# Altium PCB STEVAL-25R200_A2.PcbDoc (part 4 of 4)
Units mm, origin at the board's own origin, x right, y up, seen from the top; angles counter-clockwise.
Board outline 84.5 x 100 mm, 4 copper layers (Top Layer, F2, F3, Bottom Layer), stack 0.78 mm thick; 272 components, 152 nets, 679 pads, 380 vias.
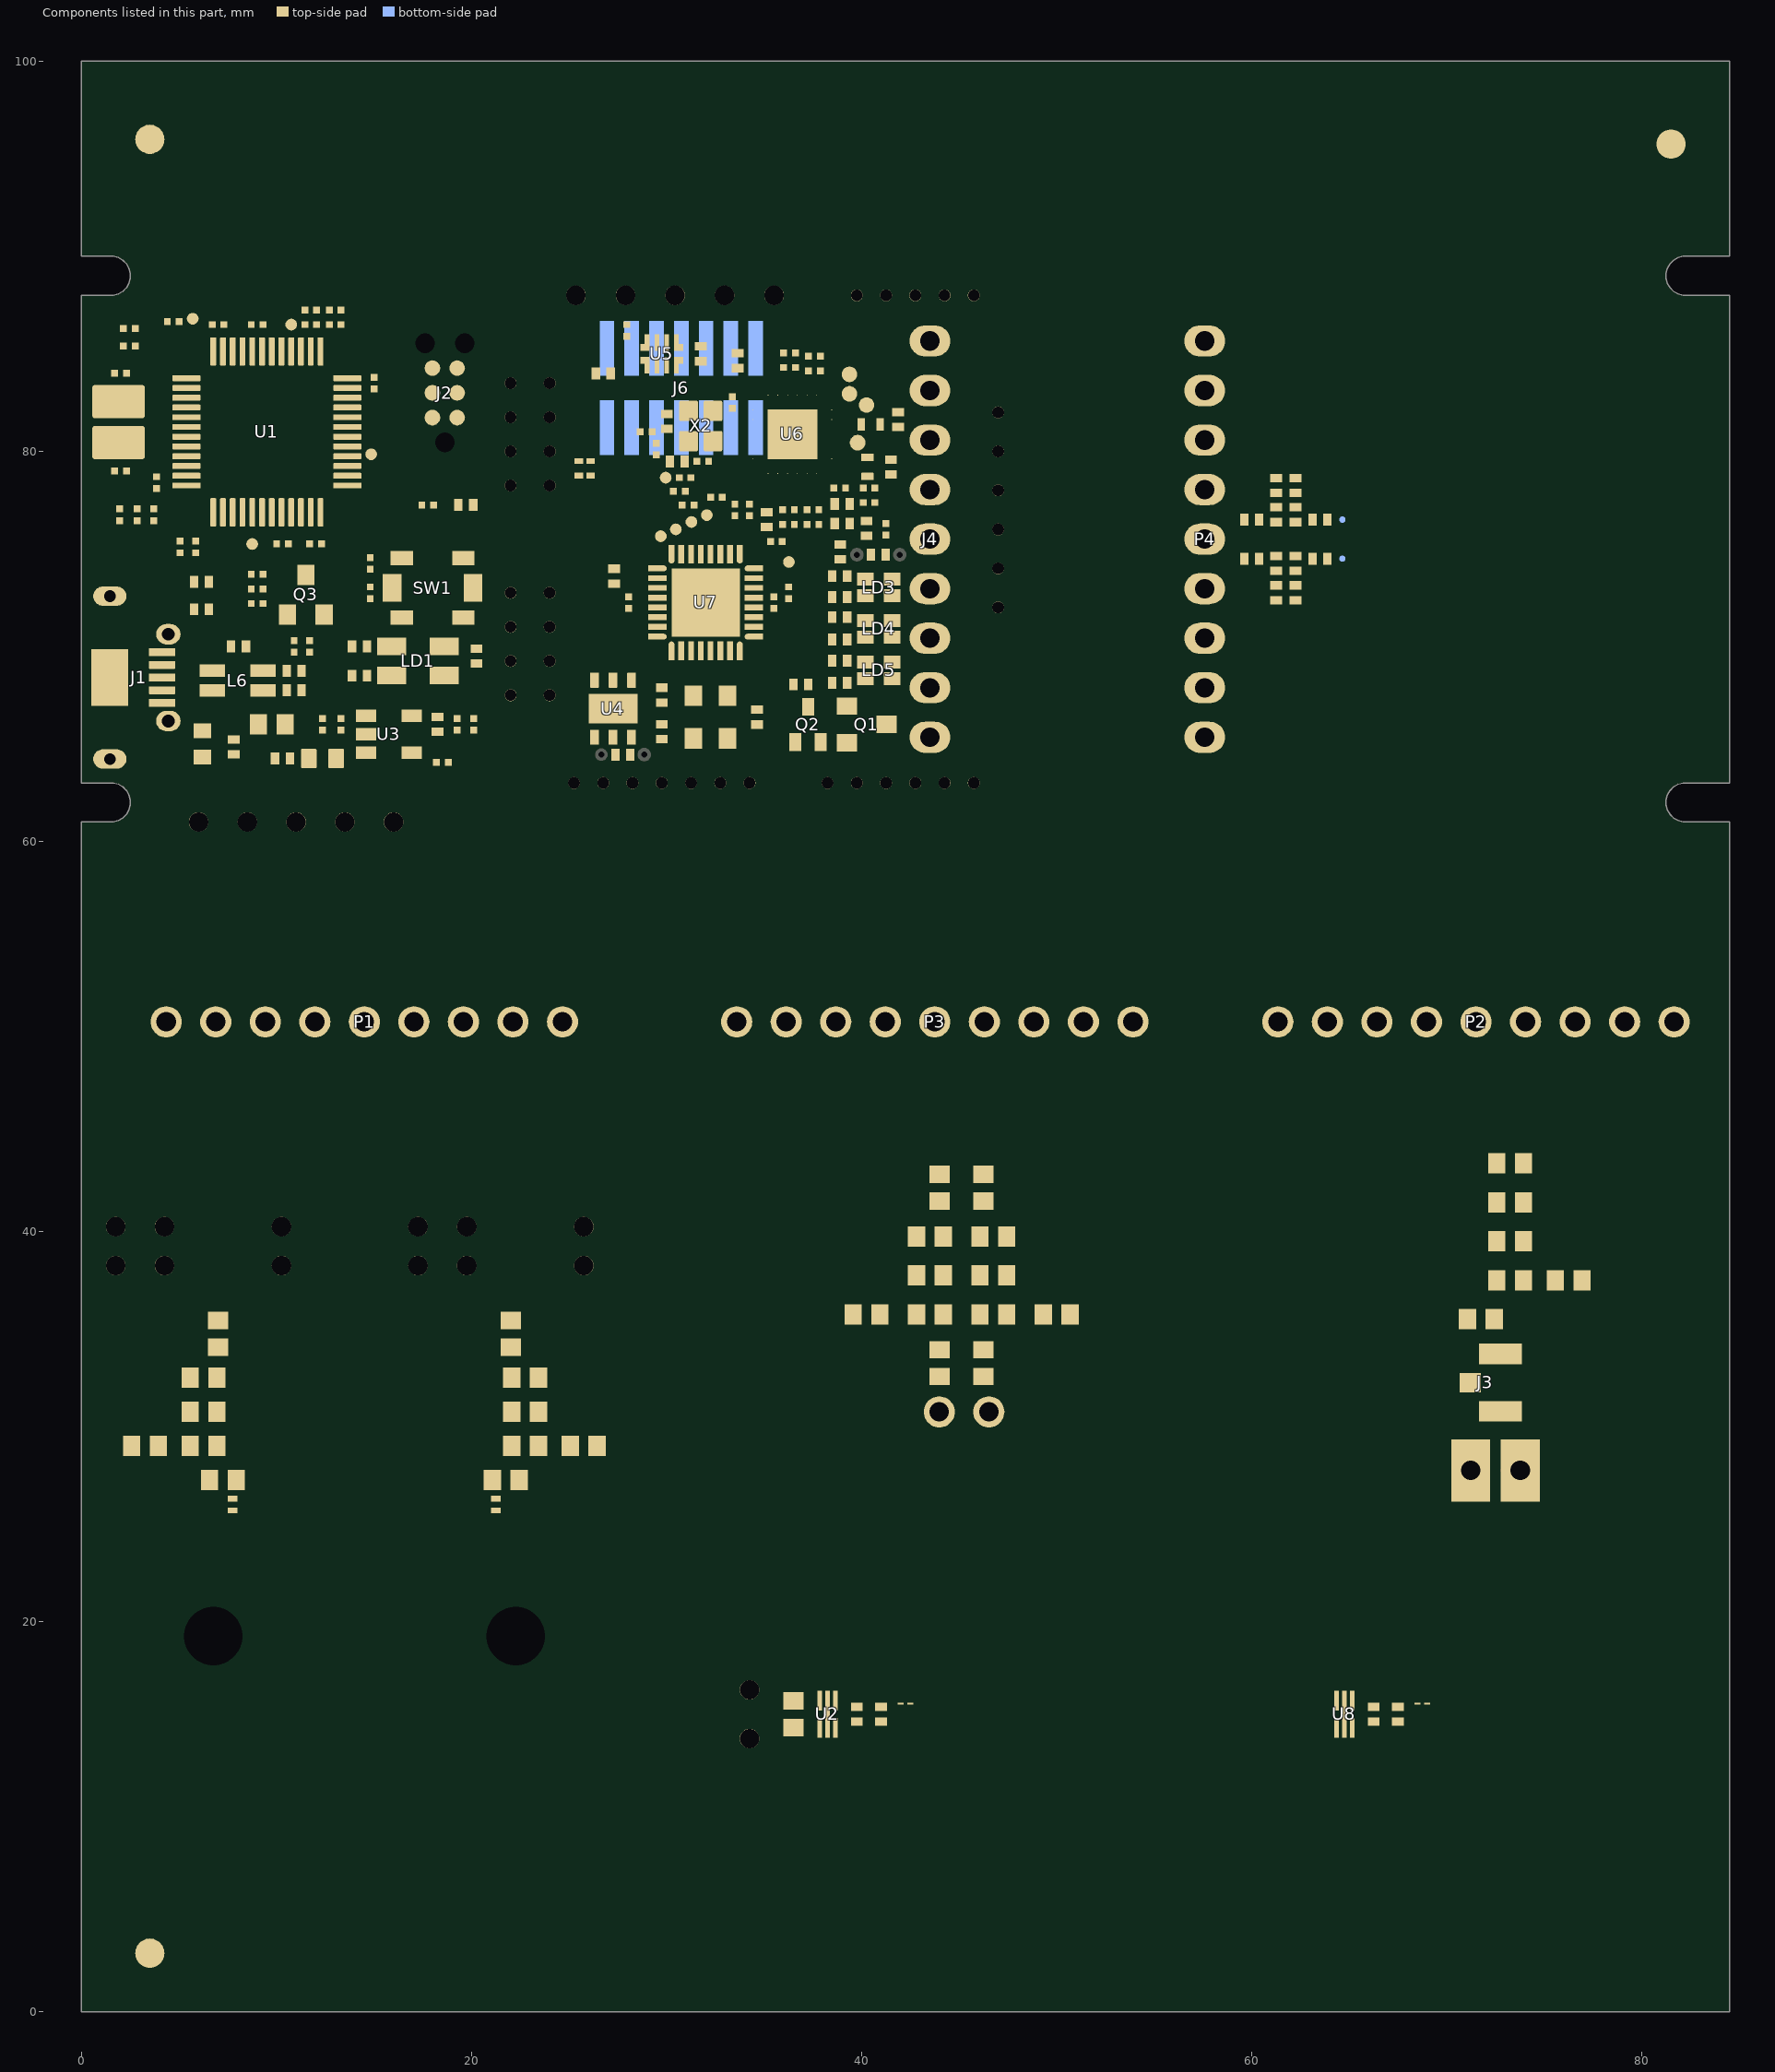
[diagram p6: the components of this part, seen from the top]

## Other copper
Top Layer:
  rectangle net VDD_RF: 41.075,74.4 42.25,75
  region net NetC79_2: 40.625,75 39.45,75 39.45,74.4 40.625,74.4
  region net NetR58_1: 27.525,64.75 26.35,64.75 26.35,64.15 27.525,64.15
  rectangle net VDD_RF: 27.975,64.15 29.15,64.75
  rectangle net NetJP2_2: 45.52,28.45 47.52,31.65
  rectangle net NetJP2_1: 42.98,28.45 44.98,31.65
  region net G0_VBUS: 30.95,86 30.45,86 30.45,85.7 30.95,85.7
  region net G0_GND_USB: 30.95,84.3 30.45,84.3 30.45,84 30.95,84
  rectangle net G0_GND_USB: 28.55,84 29.05,84.3
  region net GND_HUB: 27.445,24.445 ccw(c25.5,22.5) 25.5,25.25 23.75,25.25 cw(c23.75,25.5) 23.573,25.323 cw(c23.75,25.5) 23.5,25.5 23.5,25.8 23,25.8 23,25.5 ccw(c23.75,25.5) 23.22,24.97 ccw(c23.75,25.5) 23.75,24.75 25.5,24.75 cw(c25.5,22.5) 27.091,24.091 cw(c25.5,22.5) 27.75,22.5 27.75,16 cw(c25.5,16) 27.091,14.409 cw(c25.5,16) 25.5,13.75 23.076,13.75 21.702,14.666 ccw(c21.424,14.25) 21.569,14.729 ccw(c21.424,14.25) 21.424,14.75 19,14.75 cw(c19,16) 18.116,15.116 cw(c19,16) 17.75,16 17.75,22.5 cw(c19,22.5) 18.116,23.384 cw(c19,22.5) 19,23.75 25.5,23.75 cw(c25.5,22.5) 26.384,23.384 cw(c25.5,22.5) 26.75,22.5 26.75,16 cw(c25.5,16) 26.384,15.116 cw(c25.5,16) 25.5,14.75 23.076,14.75 21.702,15.666 ccw(c21.424,15.25) 21.569,15.729 ccw(c21.424,15.25) 21.424,15.75 19,15.75 cw(c19,16) 18.823,15.823 cw(c19,16) 18.75,16 18.75,22.5 cw(c19,22.5) 18.823,22.677 cw(c19,22.5) 19,22.75 25.5,22.75 cw(c25.5,22.5) 25.677,22.677 cw(c25.5,22.5) 25.75,22.5 25.75,16 cw(c25.5,16) 25.677,15.823 cw(c25.5,16) 25.5,15.75 23.309,15.75 22.362,16.224 ccw(c22.25,16) 22.026,16.112 ccw(c22.25,16) 22.138,15.776 23.085,15.303 ccw(c23.309,15.75) 23.194,15.263 ccw(c23.309,15.75) 23.309,15.25 25.5,15.25 ccw(c25.5,16) 26.03,15.47 ccw(c25.5,16) 26.25,16 26.25,22.5 ccw(c25.5,22.5) 26.03,23.03 ccw(c25.5,22.5) 25.5,23.25 19,23.25 ccw(c19,22.5) 18.47,23.03 ccw(c19,22.5) 18.25,22.5 18.25,16 ccw(c19,16) 18.47,15.47 ccw(c19,16) 19,15.25 21.424,15.25 22.798,14.334 ccw(c23.076,14.75) 22.931,14.271 ccw(c23.076,14.75) 23.076,14.25 25.5,14.25 ccw(c25.5,16) 26.737,14.763 ccw(c25.5,16) 27.25,16 27.25,22.5 ccw(c25.5,22.5) 26.737,23.737 ccw(c25.5,22.5) 25.5,24.25 19,24.25 ccw(c19,22.5) 17.763,23.737 ccw(c19,22.5) 17.25,22.5 17.25,16 ccw(c19,16) 17.763,14.763 ccw(c19,16) 19,14.25 21.424,14.25 22.798,13.334 ccw(c23.076,13.75) 22.931,13.271 ccw(c23.076,13.75) 23.076,13.25 25.5,13.25 ccw(c25.5,16) 27.445,14.055 ccw(c25.5,16) 28.25,16 28.25,22.5 ccw(c25.5,22.5)
  region net GND_HUB: 21.5,25.8 21,25.8 21,25.5 cw(c20.75,25.5) 20.927,25.323 cw(c20.75,25.5) 20.75,25.25 19,25.25 ccw(c19,22.5) 17.055,24.445 ccw(c19,22.5) 16.25,22.5 16.25,16 ccw(c19,16) 17.055,14.055 ccw(c19,16) 19,13.25 21.191,13.25 22.138,12.776 ccw(c22.25,13) 22.474,12.888 ccw(c22.25,13) 22.362,13.224 21.415,13.697 ccw(c21.191,13.251) 21.306,13.737 ccw(c21.191,13.251) 21.191,13.75 19,13.75 cw(c19,16) 17.409,14.409 cw(c19,16) 16.75,16 16.75,22.5 cw(c19,22.5) 17.409,24.091 cw(c19,22.5) 19,24.75 20.75,24.75 ccw(c20.75,25.5) 21.28,24.97 ccw(c20.75,25.5) 21.5,25.5
  region net GND_HUB: 6,25.8 5.5,25.8 5.5,25.5 cw(c5.25,25.5) 5.427,25.323 cw(c5.25,25.5) 5.25,25.25 3.5,25.25 ccw(c3.5,22.5) 1.555,24.445 ccw(c3.5,22.5) 0.75,22.5 0.75,16 ccw(c3.5,16) 1.555,14.055 ccw(c3.5,16) 3.5,13.25 5.691,13.25 6.638,12.776 ccw(c6.75,13) 6.974,12.888 ccw(c6.75,13) 6.862,13.224 5.915,13.697 ccw(c5.691,13.25) 5.806,13.737 ccw(c5.691,13.25) 5.691,13.75 3.5,13.75 cw(c3.5,16) 1.909,14.409 cw(c3.5,16) 1.25,16 1.25,22.5 cw(c3.5,22.5) 1.909,24.091 cw(c3.5,22.5) 3.5,24.75 5.25,24.75 ccw(c5.25,25.5) 5.78,24.97 ccw(c5.25,25.5) 6,25.5
  region net GND_HUB: 11.945,24.445 ccw(c10,22.5) 10,25.25 8.25,25.25 cw(c8.25,25.5) 8.073,25.323 cw(c8.25,25.5) 8,25.5 8,25.8 7.5,25.8 7.5,25.5 ccw(c8.25,25.5) 7.72,24.97 ccw(c8.25,25.5) 8.25,24.75 10,24.75 cw(c10,22.5) 11.591,24.091 cw(c10,22.5) 12.25,22.5 12.25,16 cw(c10,16) 11.591,14.409 cw(c10,16) 10,13.75 7.576,13.75 6.202,14.666 ccw(c5.925,14.25) 6.069,14.729 ccw(c5.924,14.251) 5.924,14.75 3.5,14.75 cw(c3.5,16) 2.616,15.116 cw(c3.5,16) 2.25,16 2.25,22.5 cw(c3.5,22.5) 2.616,23.384 cw(c3.5,22.5) 3.5,23.75 10,23.75 cw(c10,22.5) 10.884,23.384 cw(c10,22.5) 11.25,22.5 11.25,16 cw(c10,16) 10.884,15.116 cw(c10,16) 10,14.75 7.576,14.75 6.202,15.666 ccw(c5.925,15.25) 6.069,15.729 ccw(c5.924,15.251) 5.924,15.75 3.5,15.75 cw(c3.5,16) 3.323,15.823 cw(c3.5,16) 3.25,16 3.25,22.5 cw(c3.5,22.5) 3.323,22.677 cw(c3.5,22.5) 3.5,22.75 10,22.75 cw(c10,22.5) 10.177,22.677 cw(c10,22.5) 10.25,22.5 10.25,16 cw(c10,16) 10.177,15.823 cw(c10,16) 10,15.75 7.809,15.75 6.862,16.224 ccw(c6.75,16) 6.526,16.112 ccw(c6.75,16) 6.638,15.776 7.585,15.303 ccw(c7.809,15.75) 7.694,15.263 ccw(c7.809,15.75) 7.809,15.25 10,15.25 ccw(c10,16) 10.53,15.47 ccw(c10,16) 10.75,16 10.75,22.5 ccw(c10,22.5) 10.53,23.03 ccw(c10,22.5) 10,23.25 3.5,23.25 ccw(c3.5,22.5) 2.97,23.03 ccw(c3.5,22.5) 2.75,22.5 2.75,16 ccw(c3.5,16) 2.97,15.47 ccw(c3.5,16) 3.5,15.25 5.924,15.25 7.298,14.334 ccw(c7.576,14.75) 7.431,14.271 ccw(c7.576,14.75) 7.576,14.25 10,14.25 ccw(c10,16) 11.237,14.763 ccw(c10,16) 11.75,16 11.75,22.5 ccw(c10,22.5) 11.237,23.737 ccw(c10,22.5) 10,24.25 3.5,24.25 ccw(c3.5,22.5) 2.263,23.737 ccw(c3.5,22.5) 1.75,22.5 1.75,16 ccw(c3.5,16) 2.263,14.763 ccw(c3.5,16) 3.5,14.25 5.924,14.25 7.298,13.334 ccw(c7.576,13.75) 7.431,13.271 ccw(c7.576,13.75) 7.576,13.25 10,13.25 ccw(c10,16) 11.945,14.055 ccw(c10,16) 12.75,16 12.75,22.5 ccw(c10,22.5)
  text ".text_ident_couches" at 25.5,108.5 h1.5
  text "- TOP LAYER -" at 30,104.25 h1.5
F2:
  pour cut-out: 70.65,32.85 71.65,32.85 71.65,33.15 73.85,33.15 73.85,31.35 71.65,31.35 71.65,31.65 70.65,31.65
  text ".text_ident_couches" at 25.5,108.5 h1.5
  text "- LAYER 2 -" at 30.75,104.25 h1.5
F3:
  pour cut-out: 70.65,32.85 71.65,32.85 71.65,33.15 73.85,33.15 73.85,31.35 71.65,31.35 71.65,31.65 70.65,31.65
  text ".text_ident_couches" at 54.8,108.25 h1.5
  text "- LAYER 3 -" at 47.75,104.25 h1.5
Bottom Layer:
  region net GND_HUB: 27.445,24.445 cw(c25.5,22.5) 28.25,22.5 28.25,16 cw(c25.5,16) 27.445,14.055 cw(c25.5,16) 25.5,13.25 23.309,13.25 22.362,12.776 cw(c22.25,13) 22.026,12.888 cw(c22.25,13) 22.138,13.224 23.085,13.697 cw(c23.309,13.25) 23.194,13.737 cw(c23.309,13.25) 23.309,13.75 25.5,13.75 ccw(c25.5,16) 27.091,14.409 ccw(c25.5,16) 27.75,16 27.75,22.5 ccw(c25.5,22.5) 27.091,24.091 ccw(c25.5,22.5) 25.5,24.75 19,24.75 ccw(c19,22.5) 17.409,24.091 ccw(c19,22.5) 16.75,22.5 16.75,16 ccw(c19,16) 17.409,14.409 ccw(c19,16) 19,13.75 21.424,13.75 22.798,14.666 cw(c23.076,14.25) 22.931,14.729 cw(c23.076,14.25) 23.076,14.75 25.5,14.75 ccw(c25.5,16) 26.384,15.116 ccw(c25.5,16) 26.75,16 26.75,22.5 ccw(c25.5,22.5) 26.384,23.384 ccw(c25.5,22.5) 25.5,23.75 19,23.75 ccw(c19,22.5) 18.116,23.384 ccw(c19,22.5) 17.75,22.5 17.75,16 ccw(c19,16) 18.116,15.116 ccw(c19,16) 19,14.75 21.424,14.75 22.798,15.666 cw(c23.076,15.25) 22.931,15.729 cw(c23.076,15.25) 23.076,15.75 25.5,15.75 ccw(c25.5,16) 25.677,15.823 ccw(c25.5,16) 25.75,16 25.75,22.5 ccw(c25.5,22.5) 25.677,22.677 ccw(c25.5,22.5) 25.5,22.75 19,22.75 ccw(c19,22.5) 18.823,22.677 ccw(c19,22.5) 18.75,22.5 18.75,16 ccw(c19,16) 18.823,15.823 ccw(c19,16) 19,15.75 21.191,15.75 22.138,16.224 cw(c22.25,16) 22.474,16.112 cw(c22.25,16) 22.362,15.776 21.415,15.303 cw(c21.191,15.75) 21.306,15.263 cw(c21.191,15.75) 21.191,15.25 19,15.25 cw(c19,16) 18.47,15.47 cw(c19,16) 18.25,16 18.25,22.5 cw(c19,22.5) 18.47,23.03 cw(c19,22.5) 19,23.25 25.5,23.25 cw(c25.5,22.5) 26.03,23.03 cw(c25.5,22.5) 26.25,22.5 26.25,16 cw(c25.5,16) 26.03,15.47 cw(c25.5,16) 25.5,15.25 23.076,15.25 21.702,14.334 cw(c21.424,14.75) 21.569,14.271 cw(c21.424,14.75) 21.424,14.25 19,14.25 cw(c19,16) 17.763,14.763 cw(c19,16) 17.25,16 17.25,22.5 cw(c19,22.5) 17.763,23.737 cw(c19,22.5) 19,24.25 25.5,24.25 cw(c25.5,22.5) 26.737,23.737 cw(c25.5,22.5) 27.25,22.5 27.25,16 cw(c25.5,16) 26.737,14.763 cw(c25.5,16) 25.5,14.25 23.076,14.25 21.702,13.334 cw(c21.424,13.75) 21.569,13.271 cw(c21.424,13.75) 21.424,13.25 19,13.25 cw(c19,16) 17.055,14.055 cw(c19,16) 16.25,16 16.25,22.5 cw(c19,22.5) 17.055,24.445 cw(c19,22.5) 19,25.25 25.5,25.25 cw(c25.5,22.5)
  region net GND_HUB: 11.945,24.445 cw(c10,22.5) 12.75,22.5 12.75,16 cw(c10,16) 11.945,14.055 cw(c10,16) 10,13.25 7.809,13.25 6.862,12.776 cw(c6.75,13) 6.526,12.888 cw(c6.75,13) 6.638,13.224 7.585,13.697 cw(c7.809,13.25) 7.694,13.737 cw(c7.809,13.25) 7.809,13.75 10,13.75 ccw(c10,16) 11.591,14.409 ccw(c10,16) 12.25,16 12.25,22.5 ccw(c10,22.5) 11.591,24.091 ccw(c10,22.5) 10,24.75 3.5,24.75 ccw(c3.5,22.5) 1.909,24.091 ccw(c3.5,22.5) 1.25,22.5 1.25,16 ccw(c3.5,16) 1.909,14.409 ccw(c3.5,16) 3.5,13.75 5.924,13.75 7.298,14.666 cw(c7.576,14.25) 7.431,14.729 cw(c7.576,14.25) 7.576,14.75 10,14.75 ccw(c10,16) 10.884,15.116 ccw(c10,16) 11.25,16 11.25,22.5 ccw(c10,22.5) 10.884,23.384 ccw(c10,22.5) 10,23.75 3.5,23.75 ccw(c3.5,22.5) 2.616,23.384 ccw(c3.5,22.5) 2.25,22.5 2.25,16 ccw(c3.5,16) 2.616,15.116 ccw(c3.5,16) 3.5,14.75 5.924,14.75 7.298,15.666 cw(c7.576,15.25) 7.431,15.729 cw(c7.576,15.25) 7.576,15.75 10,15.75 ccw(c10,16) 10.177,15.823 ccw(c10,16) 10.25,16 10.25,22.5 ccw(c10,22.5) 10.177,22.677 ccw(c10,22.5) 10,22.75 3.5,22.75 ccw(c3.5,22.5) 3.323,22.677 ccw(c3.5,22.5) 3.25,22.5 3.25,16 ccw(c3.5,16) 3.323,15.823 ccw(c3.5,16) 3.5,15.75 5.691,15.75 6.638,16.224 cw(c6.75,16) 6.974,16.112 cw(c6.75,16) 6.862,15.776 5.915,15.303 cw(c5.691,15.75) 5.806,15.263 cw(c5.691,15.75) 5.691,15.25 3.5,15.25 cw(c3.5,16) 2.97,15.47 cw(c3.5,16) 2.75,16 2.75,22.5 cw(c3.5,22.5) 2.97,23.03 cw(c3.5,22.5) 3.5,23.25 10,23.25 cw(c10,22.5) 10.53,23.03 cw(c10,22.5) 10.75,22.5 10.75,16 cw(c10,16) 10.53,15.47 cw(c10,16) 10,15.25 7.576,15.25 6.202,14.334 cw(c5.924,14.75) 6.069,14.271 cw(c5.924,14.75) 5.924,14.25 3.5,14.25 cw(c3.5,16) 2.263,14.763 cw(c3.5,16) 1.75,16 1.75,22.5 cw(c3.5,22.5) 2.263,23.737 cw(c3.5,22.5) 3.5,24.25 10,24.25 cw(c10,22.5) 11.237,23.737 cw(c10,22.5) 11.75,22.5 11.75,16 cw(c10,16) 11.237,14.763 cw(c10,16) 10,14.25 7.576,14.25 6.202,13.334 cw(c5.924,13.75) 6.069,13.271 cw(c5.924,13.75) 5.924,13.25 3.5,13.25 cw(c3.5,16) 1.555,14.055 cw(c3.5,16) 0.75,16 0.75,22.5 cw(c3.5,22.5) 1.555,24.445 cw(c3.5,22.5) 3.5,25.25 10,25.25 cw(c10,22.5)
  text ".text_ident_couches" at 54.6,108.25 h1.5
  text "- BOTTOM LAYER -" at 50.25,104.25 h1.5

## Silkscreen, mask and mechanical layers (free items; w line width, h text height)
Top Overlay:
  drawing of 607 lines, arcs and shapes, not listed
  text ".text_ident_couches" at 25.5,108.5 h1.5
  text "- TOP OVERLAY -" at 28.75,104.25 h1.5
  text "STEVAL$25R200AA" at 69.108,98.3 h1.8
  text "STEVAL-25R200A" at 25.833,93.3 h6
  text "STLink" at 8.118,91 h2
  text "ST25R200 Module" at 27.25,91 h2
  text "Main NFC Antenna" at 58,91 h2
  text "GND" at 17.28,86.55 h1.3
  text "USB" at 32.347,85.53 h1.7
  text "TCK" at 16.798,85.231 h1.3 r90
  text "RST" at 21.5,85.23 h1.3 r90
  text "ANT" at 42.2,83.107 h1.7 r90
  text "VCC" at 20.587,78.156 h1.3 r90
  text "TMS" at 17.15,78.13 h1.3 r90
  text "ST25R200" at 28.26,76.172 h1.4 r90
  text "RESET" at 15.228,75.15 h1.7
  text "USB" at 1.075,73.3 h1.7
  text "L1" at 36.8,73.31 h1.3
  text "ST25" at 72.893,72.532 h1.65
  text "L2" at 36.8,71.13 h1.3
  text "L3" at 36.8,68.92 h1.3
  text "STEVAL-25R200" at 26.74,68.685 h1.38 r90
  text "NFC Antenna 20x20mm" at 65.469,64.212 h1.6
  text "Dual Antenna Hub" at 2.25,47.5 h3
  text "Flexible Antenna" at 33,47.5 h3
  text "50 Ohms Antenna Interface" at 59.5,45 h3
  text "Flex Antenna" at 41.4,21.412 h1.7 r90
  text "ANT1" at 3.213,7.5 h2
  text "ANT2" at 18.562,7.5 h2
  text "Tag1 : ST25TV" at 33.938,7 h2
  text "Tag2 : ST25TN" at 61.938,7 h2
  text "12x12mm" at 1.604,6 h1.6
  text "12x12mm" at 17.604,6 h1.6
  text "10x5mm" at 38.604,6 h1.6
  text "10x5mm" at 66.604,6 h1.6
  text "ST25R200 Evaluation Board : NFC made easy" at 7.134,1 h3.8
Bottom Overlay:
  drawing of 432 lines, arcs and shapes, not listed
  text ".text_ident_couches" at 54.4,108.25 h1.5
  text "- BOTTOM OVERLAY -" at 53,104.25 h1.5
  text "MM0005A1" at 20.2,86.517 h1.5
  text "FCC ID: YCPR200AD1" at 9.23,85.873 h2.3 r90
  text "IC: 8976A-R200AD1" at 11.19,85.858 h2.3 r90
  text "MM0003A1" at 82.95,85.817 h1.5
  text "STEVAL-25R200SA" at 7.33,85.623 h2.3 r90
  text "GND" at 56.15,85.12 h1.5
  text "FOR EVALUATION ONLY" at 13.67,84.52 h1.8 r90
  text "VDD" at 36.55,83.382 h1.5 r270
  text "DAC" at 37.8,83.357 h1.5 r270
  text "ADC" at 39,83.26 h1.5 r270
  text "VCCSTLK" at 20.65,83.05 h1.5
  text "MM0004A1" at 33.4,82.816 h1.39
  text "RFI2" at 56.05,82.6 h1.5
  text "SCL" at 40.2,82.487 h1.5 r270
  text "SDA" at 41.298,82.475 h1.5 r270
  text "GND" at 20.65,81.25 h1.5
  text "GND" at 44.85,80.947 h1.5 r270
  text "STLink" at 25.3,80.661 h1.39 r270
  text "GND" at 56.15,80.04 h1.5
  text "I2" at 44.9,79.55 h1.5 r270
  text "RX" at 20.91,79.33 h1.5
  text "UART" at 18.35,78.4 h1.5
  text "TX" at 20.9,77.78 h1.5
  text "RFO2" at 56.15,77.5 h1.5
  text "O2" at 44.8,77.15 h1.5 r270
  text "O1" at 44.8,75.15 h1.5 r270
  text "RFO1" at 56.162,74.95 h1.5
  text "I1" at 44.8,73.6 h1.5 r270
  text "GND" at 56.15,72.42 h1.5
  text "5V_USB / CHGR" at 20.7,71.93 h1.5
  text "STEVAL-25R200A" at 82.013,71.62 h2.8
  text "SWDIO" at 20.65,70.55 h1.5
  text "GND" at 44.8,70.247 h1.5 r270
  text "RFI1" at 56.041,69.95 h1.5
  text "TCK" at 20.65,68.8 h1.5
  text "I2S2" at 28.53,67.39 h1.5
  text "GND" at 56.15,67.34 h1.5
  text "AUXIN" at 41.01,67.22 h1.5
  text "RST" at 20.65,67.05 h1.5
  text "SD" at 26.2,65.02 h1.5 r270
  text "AUXOUT" at 45.8,64.9 h1.5 r270
  text "CK" at 27.75,64.82 h1.5 r270
  text "GND" at 56.15,64.8 h1.5
  text "GND" at 44.7,64.6 h1.5 r270
  text "TX" at 37.806,64.204 h1.5 r270
  text "RX" at 39.207,64.204 h1.5 r270
  text "WS" at 24.8,64.147 h1.5 r270
  text "GND" at 29.36,64.15 h1.5 r270
  text "5VUSB" at 30.8,64.147 h1.5 r270
  text "5VUSB" at 32.3,64.147 h1.5 r270
  text "GND" at 33.8,64.147 h1.5 r270
  text "GND" at 40.645,64.114 h1.5 r270
  text "STEVAL$25R200AA" at 83.564,63.69 h2.2
  text "MM0006A1" at 28,58.217 h1.5
  text "MM0009A1" at 55.75,58.217 h1.5
  text "MM0010A1" at 83.7,58.217 h1.5
  text "RFI1" at 7.99,56.967 h1.5 r270
  text "RFI2" at 15.61,56.67 h1.5 r270
  text "GND" at 5.51,56.567 h1.5 r270
  text "RFO1" at 10.52,56.307 h1.5 r270
  text "RFO2" at 13.08,56.06 h1.5 r270
  text "GND" at 3.8,51.8 h1.5 r270
  text "GND" at 6.34,51.8 h1.5 r270
  text "RFI1" at 8.95,51.8 h1.5 r270
  text "GND" at 11.42,51.8 h1.5 r270
  text "RFO1" at 13.95,51.8 h1.5 r270
  text "RFO2" at 16.5,51.8 h1.5 r270
  text "GND" at 19.04,51.8 h1.5 r270
  text "RFI2" at 21.6,51.8 h1.5 r270
  text "GND" at 24.12,51.8 h1.5 r270
  text "RFI1" at 38.2,46.909 h1.5 r270
  text "RFI2" at 50.85,46.758 h1.5 r270
  text "RFI2" at 78.6,46.758 h1.5 r270
  text "RFO1" at 43.2,46.238 h1.5 r270
  text "GND" at 33.05,46.087 h1.5 r270
  text "GND" at 35.59,46.087 h1.5 r270
  text "GND" at 40.67,46.087 h1.5 r270
  text "RFO2" at 45.75,46.087 h1.5 r270
  text "GND" at 48.29,46.087 h1.5 r270
  text "GND" at 53.37,46.087 h1.5 r270
  text "GND" at 60.8,46.087 h1.5 r270
  text "GND" at 63.34,46.087 h1.5 r270
  text "GND" at 68.42,46.087 h1.5 r270
  text "RFO2" at 73.5,46.087 h1.5 r270
  text "GND" at 76.04,46.087 h1.5 r270
  text "GND" at 81.12,46.087 h1.5 r270
  text "ANT1" at 8.5,46 h2
  text "ANT2" at 23.5,46 h2
  text "GND" at 1.3,41.647 h1.5 r270
  text "RFI1" at 3.8,41.647 h1.5 r270
  text "RFO1" at 9.8,41.647 h1.5 r270
  text "GND" at 16.8,41.647 h1.5 r270
  text "RFO2" at 19.3,41.647 h1.5 r270
  text "RFI2" at 25.3,41.647 h1.5 r270
  text "GND" at 1.25,33.647 h1.5 r270
  text "RFI1" at 3.75,33.647 h1.5 r270
  text "GND" at 16.75,33.647 h1.5 r270
  text "RFI2" at 25.25,33.647 h1.5 r270
  text "RFO1" at 9.75,33.238 h1.5 r270
  text "RFO2" at 19.25,33.087 h1.5 r270
  text "MM0011A1" at 52.8,16.767 h1.5
  text "MM0012A1" at 79.3,16.767 h1.5
  text "TD1" at 38.173,16.01 h1.5
  text "TD0" at 38.473,13.49 h1.5
  text "MM0007A1" at 13,12.717 h1.5
  text "MM0008A1" at 28.5,12.717 h1.5
Top Paste:
  drawing of 902 lines, arcs and shapes, not listed
  text ".text_ident_couches" at 25.5,108.5 h1.5
  text "- TOP PASTE MASK -" at 26.75,104.25 h1.5
Top Solder:
  text ".text_ident_couches" at 25.5,108.5 h1.5
  text "- TOP SOLDER MASK -" at 26.25,104.25 h1.5
Bottom Solder:
  text ".text_ident_couches" at 54.1,108.25 h1.5
  text "- BOTTOM SOLDER MASK -" at 55.75,104.25 h1.5
Top Assembly:
  lines w0.1: 27.9,79.47 29.75,79.47 ; 27.91,78.15 30.04,78.15 30.35,78.46 ; 29.41,79.05 31.62,79.05 31.75,79.18 ; 35,62 37.5,62 ; 36.3,75.95 36.3,75.05 36.8,74.55 36.8,74.4 ; 37.6,68.75 37.85,68.75 38.1,68.5 ; 37.95,75.15 38,75.15 38.7,75.85 ; 39.78,76.99 39.96,76.81 42.42,76.81 ; 40.75,75.45 41,75.2 42.2,75.2 42.9,74.5 43.5,74.5 ; 41.25,74.25 41.4,74.1 42,74.1 ; 41.55,67.75 41.55,67.15 42.05,66.65 42.3,66.65 ; 41.9,70 42.75,69.15 42.9,69.15 ; 41.95,72.15 42.35,71.75 42.7,71.75 ; 46.5,62 111.5,62
  lines w0.15: 10.56,65.12 12.01,65.12 12.24,64.89 ; 12.34,86.18 12.61,85.91 13.85,85.91 ; 26.2,74.53 28.64,76.97 28.65,76.97 ; 28.08,76.41 30.09,76.41 ; 29.24,76.02 31.16,76.88 ; 33.39,78.63 33.68,78.34 33.68,78.15 34.14,77.69 ; 33.79,79.1 34.04,78.85 34.04,78.36 35.09,77.31 ; 34.39,75.62 34.54,75.62 34.79,75.37 34.97,75.37 ; 38.29,84.13 38.63,84.47 38.63,84.94 ; 39.73,83.42 40.43,84.12 40.68,84.12 ; 46.55,78.7 46.75,78.9 49.3,78.9 49.5,78.7 ; 47.85,72 49.3,72 ; 47.85,74 49.3,74 ; 47.85,76 49.25,76 49.45,76.2 ; 47.85,80 49.25,80 49.45,79.8 ; 47.85,82 49.3,82 ; 60.37,78 60.37,77.41 60.75,77.03 ; 60.4,73.11 60.4,73.45 60.72,73.77 ; 62.74,77.01 63.45,77.72 63.45,77.95 ; 62.76,73.81 63.25,73.32 63.25,73.12
  lines w0.2: -9,91.5 -9,109 ; -9,93.75 -8.75,93.75 21.25,93.75 23,92 23,84.75 ; 23,73.85 23,77 ; 41.6,34.2 42.3,34.2 43,34.9 ; 47.4,34.8 48.25,33.95 48.75,33.95
  text "VCC_STLK" at -18.376,107.688 h1.5
  text "GND" at -18.376,105.938 h1.5
  text "UART_RX" at -18.376,104.188 h1.5
  text "UART_TX" at -18.376,102.438 h1.5
  text "5V_USB_CHGR" at -19.31,99.038 h1.5
  text "T_SWDIO_IN" at -18.376,97.438 h1.5
  text "T_JTCK" at -18.376,95.688 h1.5
  text "N_RST_G0" at -18.376,93.938 h1.5
  text "G0_GND_USB" at 26,90.31 h1.5 r90
  text "USB_ID" at 28.54,90.31 h1.5 r90
  text "USB_IN_P" at 31.08,90.31 h1.5 r90
  text "USB_IN_N" at 33.62,90.31 h1.5 r90
  text "G0_VBUS" at 36.16,90.31 h1.5 r90
  text "VDD_STM32" at 40.4,90.31 h1.5 r90
  text "DAC_OUT1" at 41.9,90.31 h1.5 r90
  text "ADC1_IN1" at 43.4,90.31 h1.5 r90
  text "I2C1_SCL" at 44.9,90.31 h1.5 r90
  text "I2C1_SDA" at 46.4,90.31 h1.5 r90
  text "J4/P4 ASSEMBLY :" at 91.2,84.75 h3
  text "GND" at 49.5,81.502 h1.5
  text "RFI2" at 49.65,79.352 h1.5
  text "RFO2" at 49.7,78.252 h1.5
  text "RFO1" at 49.65,75.752 h1.5
  text "J4 AND P4 SHALL BE PLUGGED TOGETHER / BEFORE BEING SOLDERED" at 97.45,74.4 h3
  text "RFI1" at 49.5,73.502 h1.5
  text "GND" at 49.5,71.502 h1.5
  text "5V_USB_CHGR" at 98.038,52.969 h1.3 r90
  text "5V_USB_CHGR" at 99.538,52.969 h1.3 r90
  text "I2S2_WS" at 92.022,52.531 h1.5 r90
  text "I2S2_SD" at 93.522,52.531 h1.5 r90
  text "I2S2_CK" at 95.022,52.531 h1.5 r90
  text "GND" at 96.522,52.531 h1.5 r90
  text "GND" at 101.022,52.531 h1.5 r90
  text "UART6_TX" at 104.022,52.531 h1.5 r90
  text "UART6_RX" at 105.522,52.531 h1.5 r90
  text "GND" at 107.022,52.531 h1.5 r90
  text "AUX_IN" at 108.522,52.531 h1.5 r90
  text "GND" at 110.022,52.531 h1.5 r90
  text "AUX_OUT" at 111.522,52.531 h1.5 r90
  text "GND" at 6.612,50.601 h1.5 r90
  text "RFI1" at 9.112,50.601 h1.5 r90
  text "RFO1" at 11.612,50.601 h1.5 r90
  text "RFO2" at 14.112,50.601 h1.5 r90
  text "RFI2" at 16.612,50.601 h1.5 r90
  text "RFO2" at 20.332,36.131 h1.5 r90
  text "RFO1" at 10.792,35.991 h1.5 r90
  text "GND" at 2.432,35.551 h1.5 r90
  text "GND" at 17.932,35.551 h1.5 r90
  text "RFI2" at 26.312,35.561 h1.5 r90
  text "RFI1" at 4.932,35.311 h1.5 r90
  text "SB1 SOLDER BRIDGE MUST BE SHORTED BY SOLDER DROP" at 89.1,11.45 h3
  text "RoHS COMPLIANT PRODUCT" at 16.95,-45.15 h2.5
  text "TOP ASSEMBLY DRAWING" at 184.5,-123 h2
  text ".Reference" at 220,-148 h2
  text "01/02" at 278,-148.5 h2.1
Bottom Assembly:
  text "BOTTOM ASSEMBLY DRAWING" at 16,-123 h2
  text "02/02" at -85.5,-148.5 h2
  text ".Reference" at -26.5,-148.5 h2
Drill Drawing:
  drawing of 178 lines, arcs and shapes, not listed
  text "TOP LAYER VIEW" at 12.55,109.05 h3
  text "BOARD DESIGN CONCEPTION VALUES" at 204.28,99.17 h1.75
  text "SPECIFIED VALUES ARE MINIMUM. USED VALUES MAY BE LARGER" at 194.28,96.17 h1.4
  text "EXTERNAL" at 228.515,91.41 h1.4
  text "INTERNAL" at 249.47,91.41 h1.4
  text "LAYERS" at 228.515,88.87 h1.4
  text "LAYERS" at 249.47,88.87 h1.4
  text "FINISHED HOLE" at 227.5,85 h1.4
  text "FINISHED HOLE" at 249.75,85 h1.4
  text "PLATED HOLES" at 194.225,84.425 h1.4
  text "MIN. ANNULAR RING" at 194.225,81.885 h1.4
  text "0.20mm" at 233.595,81.885 h1.4
  text "0.20mm" at 255.845,81.885 h1.4
  text "+" at 252.89,81.55 h2.1
  text "+" at 230.45,81.46 h2.1
  text "DRILL HOLE" at 229.25,78.17 h1.4
  text "DRILL HOLE" at 251.5,78.17 h1.4
  text "VIA MINIMUM" at 193.59,77.44 h1.4
  text "0.125mm" at 233.75,75.17 h1.4
  text "0.125mm" at 256,75.17 h1.4
  text "ANNULAR RING" at 193.59,74.9 h1.4
  text "+" at 230.75,74.67 h2.1
  text "+" at 253,74.67 h2.1
  text "HOLE TO HOLE" at 193.59,70.455 h1.4
  text "0.35mm" at 231,69.5 h1.4
  text "LAYERS STACK-UP" at 122.67,68.25 h2.1
  text "MINIMUM CLEARANCE" at 193.59,67.915 h1.4
  text "TOP LAYER" at 127.67,63.25 h1.75
  text "F1:17µ" at 109.92,61.875 h1.4
  text "MINIMUM TRACK WIDTH" at 193.645,58.785 h1.4
  text "0.15mm" at 248.89,58.785 h1.4
  text "F2:17µ" at 109.285,56.16 h1.4
  text "MINIMUM CLEARANCE" at 193.01,54.34 h1.4
  text "0.125mm" at 248.89,53.07 h1.4
  text "BETWEEN COPPER PARTS" at 193.01,51.8 h1.4
  text "F3:17µ" at 109.285,51.08 h1.4
  text "MINIMUM CLEARANCE BETWEEN :" at 193.335,48.77 h1.4
  text "NON-PLATED HOLES & COPPER PARTS :" at 193.335,45.77 h1.4
  text "0.50mm" at 240.335,45.77 h1.4
  text "0.80 +/-10%" at 166.75,45.75 h1.4 r90
  text "F4:17µ" at 109.285,45.365 h1.4
  text "BOARD EDGE & COPPER PARTS :" at 193.335,42.77 h1.4
  text "0.50mm" at 231.335,42.77 h1.4
  text "BOTTOM LAYER" at 124.67,40.25 h1.75
  text "SOLDER MASK EXPANSION FROM PAD EDGE :" at 193.335,39.77 h1.4
  text "0.05mm" at 246.335,39.77 h1.4
  text "VIAS PROTECTION :" at 193.25,34.75 h1.4
  text "HOLE FREE OF SOLDER MASK WITH 0.05mm EXPANSION / FROM THE DRILL HOLE EDGE" at 193.25,30 h1.4
  text "MINIMUM SOLDER MASK SLIVER" at 193.645,25.655 h1.4
  text "0.10mm" at 252.7,25.655 h1.4
  text "SPECIFIC & LOCAL VALUES" at 215.305,19.33 h1.75
  text "TO ENSURE 0.1mm MINIMUM SOLDER MASK SLIVER, PAD SOLDER" at 192.555,15.425 h1.4
  text "MASK EXPANSION IS LOCALLY REDUCED TO 0.025mm" at 192.805,12.66 h1.4
  text "SOME PLATED HOLES ARE FOR CASTELLATED PADS / THEY OVERLAP BOARD OUTLINE" at 192.5,6 h1.4
  text "DUE TO GEOMETRIC CONSTRAINTS (PRINTED ANTENNAS) MIN. TRACK WIDTH AND MIN. CLEARANCE ARE LOCALLY REDUCED TO 0.10mm" at 192.5,-2.5 h1.4
  text "DUE TO MECHANICAL CONSTRAINTS, NPTH TO COPPER CLEARANCE IS LOCALLY REDUCED TO 0.27mm" at 192.44,-9.74 h1.4
  text "PTH HOLE MIN. ANNULAR RING IS LOCALLY REDUCED TO 0.175 ON TOP LAYER" at 192.44,-15.95 h1.4
  text "NOTES WHICH REFER TO IPC6012 SPECIFICATION /  IMPLY USE OF DOCUMENT LAST REVISION" at 196.75,-24 h1.5
  text "1-" at 191.28,-31 h1.5
  text "MANUFACTURING ACCORDING TO" at 195.28,-31 h1.5
  text "IPC-6012 CLASS 2" at 235.28,-31 h1.5
  text "FOR FULL BOARD OUTLINE AND ITS CUTOUTS DEFINITION, / REFER TO BOARD GERBER FILE" at -3,-33 h2
  text "2-" at 191.28,-35 h1.5
  text "MATERIAL :" at 195.28,-35 h1.5
  text "FR4 TG 170 MINI - LOW CTE -" at 210.83,-35.1 h1.5
  text "3-" at 191.28,-39 h1.5
  text "HOLES PLATING :" at 195.28,-39 h1.5
  text "COPPER PLATING ACCORDING TO" at 218.28,-39 h1.5
  text "IPC-6012 RELATED TABLES" at 218.28,-42 h1.5
  text "4-" at 191.253,-45.248 h1.5
  text "COPPER WEIGHT : SEE LAYERS STACK-UP." at 196.968,-45.248 h1.5
  text "ACCORDING TO IPC-6012 RELATED TABLES:" at 196.968,-47.698 h1.5
  text "(INTERNAL , EXTERNAL STARTING FOIL)" at 196.968,-50.148 h1.5
  text "Symbol" at -61.808,-51.85 h1.44
  text "Count" at -51.85,-51.85 h1.44
  text "Hole Size" at -39.953,-51.85 h1.44
  text "Plated" at -25.677,-51.85 h1.44
  text "Hole Type" at -15.72,-51.85 h1.44
  text "Via/Pad" at -1.204,-51.85 h1.44
  text "Hole Length" at 10.433,-51.85 h1.44
  text "Rout Path Length" at 27.589,-51.85 h1.44
  text "5-" at 191.253,-54.378 h1.5
  text "EXTERNAL LAYERS CHEMICAL PLATING:" at 196.968,-54.378 h1.5
  text "380" at -51.85,-54.85 h1.2
  text "0.200mm" at -39.953,-54.85 h1.2
  text "PTH" at -25.677,-54.85 h1.2
  text "Round" at -15.72,-54.85 h1.2
  text "Via" at -1.204,-54.85 h1.2
  text "-" at 10.433,-54.85 h1.2
  text "-" at 27.589,-54.85 h1.2
  text "O" at -62.355,-55 h1.33
  text "GOLD OVER NICKEL ACCORDING TO" at 197.28,-57 h1.5
  text "4" at -51.85,-57.85 h1.2
  text "0.300mm" at -39.953,-57.85 h1.2
  text "PTH" at -25.677,-57.85 h1.2
  text "Round" at -15.72,-57.85 h1.2
  text "Pad" at -1.204,-57.85 h1.2
  text "-" at 10.433,-57.85 h1.2
  text "-" at 27.589,-57.85 h1.2
  text "S" at -62.355,-58 h1.33
  text "IPC6012 RELATED TABLE -  CODE ENIG" at 197.28,-60 h1.5
  text "40" at -51.85,-60.85 h1.2
  text "0.600mm" at -39.953,-60.85 h1.2
  text "PTH" at -25.677,-60.85 h1.2
  text "Round" at -15.72,-60.85 h1.2
  text "Pad" at -1.204,-60.85 h1.2
  text "-" at 10.433,-60.85 h1.2
  text "-" at 27.589,-60.85 h1.2
  text "A" at -62.355,-61 h1.33
  text "2" at -51.85,-63.85 h1.2
  text "0.600mm" at -39.953,-63.85 h1.2
  text "PTH" at -25.677,-63.85 h1.2
  text "Slot" at -15.72,-63.85 h1.2
  text "Pad" at -1.204,-63.85 h1.2
  text "1.300mm" at 10.433,-63.85 h1.2
  text "0.700mm" at 27.589,-63.85 h1.2
  text "B" at -62.355,-64 h1.33
  text "6-" at 191.363,-65.348 h1.5
  text "SOLDER RESIST :" at 197.078,-65.348 h1.5
  text "2" at -51.85,-66.85 h1.2
  text "0.650mm" at -39.953,-66.85 h1.2
  text "PTH" at -25.677,-66.85 h1.2
  text "Slot" at -15.72,-66.85 h1.2
  text "Pad" at -1.204,-66.85 h1.2
  text "0.850mm" at 10.433,-66.85 h1.2
  text "0.200mm" at 27.589,-66.85 h1.2
  text "C" at -62.355,-67 h1.33
  text "LIQUID PHOTOIMAGEABLE" at 197.28,-68 h1.5
  text "TOP AND BOTTOM LAYERS" at 231.28,-68 h1.5
  text "55" at -51.85,-69.85 h1.2
  text "1.000mm" at -39.953,-69.85 h1.2
  text "PTH" at -25.677,-69.85 h1.2
  text "Round" at -15.72,-69.85 h1.2
  text "Pad" at -1.204,-69.85 h1.2
  text "-" at 10.433,-69.85 h1.2
  text "-" at 27.589,-69.85 h1.2
  text "D" at -62.355,-70 h1.33
  text "COLOR :" at 197.28,-71 h1.5
  text "DARK BLUE" at 208.28,-71 h1.5
  text "18" at -51.85,-72.85 h1.2
  text "1.000mm" at -39.953,-72.85 h1.2
  text "PTH" at -25.677,-72.85 h1.2
  text "Slot" at -15.72,-72.85 h1.2
  text "Pad" at -1.204,-72.85 h1.2
  text "1.500mm" at 10.433,-72.85 h1.2
  text "0.500mm" at 27.589,-72.85 h1.2
  text "E" at -62.355,-73 h1.33
  text "3" at -51.85,-75.85 h1.2
  text "1.000mm" at -39.953,-75.85 h1.2
  text "NPTH" at -25.677,-75.85 h1.2
  text "Round" at -15.72,-75.85 h1.2
  text "Pad" at -1.204,-75.85 h1.2
  text "-" at 10.433,-75.85 h1.2
  text "-" at 27.589,-75.85 h1.2
  text "G" at -62.355,-76 h1.33
  text "7-" at 191.363,-77.478 h1.5
  text "SILK SCREEN PRINTING" at 197.078,-77.478 h1.5
  text "TOP AND BOTTOM LAYERS" at 231.28,-78 h1.5
  text "2" at -51.85,-78.85 h1.2
  text "3.000mm" at -39.953,-78.85 h1.2
  text "NPTH" at -25.677,-78.85 h1.2
  text "Round" at -15.72,-78.85 h1.2
  text "Pad" at -1.204,-78.85 h1.2
  text "-" at 10.433,-78.85 h1.2
  text "-" at 27.589,-78.85 h1.2
  text "X" at -62.355,-79 h1.33
  text "EPOXYDE WHITE INK" at 197.28,-80 h1.5
  text "506 Total" at -51.85,-81.85 h1.2
  text "Slot definitions :" at -61.808,-84.649 h1.2
  text "Rout Path Length" at -41.294,-84.649 h1.2
  text "= Calculated from tool start centre position to tool end centre position." at -21.78,-84.649 h1.2
  text "8-" at 191.998,-85.448 h1.5
  text "PACKING PAPER WITH CORROSION INHIBITOR" at 197.078,-85.448 h1.5
  text "Hole Length" at -41.294,-86.549 h1.2
  text "= Rout Path Length + Tool Size = Slot length as defined in the PCB layout" at -27.578,-86.549 h1.2
  text "9-" at 192.048,-91.798 h1.5
  text "RoHS COMPLIANT PRODUCT" at 197.128,-91.798 h1.5
  text "Hole Size shall be taken as follow : / - PTH PAD : Finished Size / - PTH VIA : Drill Size / - Any NPTH : Drill Size" at -76,-105.25 h1.5
  text "Hole Size Tolerance (unless otherwise specified):" at -76.5,-113.75 h1.5
  text "PTH <1.6mm: +0.1/-0.05" at -73.5,-117 h1.5
  text "WARNING: / Drill letters are only intended to provide / an overview of the drill map. They may not / match with the exact holes location. / They shall not be used for drill process." at 19.5,-119 h1.5
  text "PTH >1.6mm: +0.15/-0.1" at -73.5,-120.5 h1.5
  text "DRILL DRAWING" at 190,-123 h2
  text "NPTH: +/-0.1" at -73.5,-124 h1.5
  text "Vias: No requirement regarding to the finished hole size" at -73.5,-131 h1.5
  text ".Reference" at 220.5,-148.5 h2.1
  text "01/01" at 279,-148.5 h2.1
Cartouche Top:
  drawing of 437 lines, arcs and shapes, not listed
  text "DATE" at 115.5,-108.5 h1.05
  text "EVOLUTION" at 143.5,-108.5 h1.05
  text "DESIGNER" at 178.5,-108.5 h1.05
  text "REV" at 196.5,-108.5 h1.05
  text "DATE" at 205.5,-108.5 h1.05
  text "EVOLUTION" at 231.5,-108.5 h1.05
  text "DESIGNER" at 267.5,-108.5 h1.05
  text "REV" at 285.197,-108.701 h1.05
  text "TITLE :" at 117.137,-115.601 h2.1
  text ".Title" at 190.824,-116.216 h2.1
  text "GENERAL TOL." at 269.5,-116.5 h1.4
  text "+/- 0,2" at 271.5,-122.5 h1.75
  text "DOCUMENT :" at 117.137,-123.221 h2.1
  text "CHECKED" at 217.5,-128.5 h1.05
  text "APPROVED" at 245.5,-128.5 h1.05
  text "SCALE :" at 141.5,-129.5 h1.05
  text "DRAWN :" at 168.5,-129.5 h1.4
  text "BE TECH" at 191.5,-129.5 h1.4
  text "1/1" at 153.321,-130.216 h2.1
  text "DATE :" at 169.5,-133.5 h1.4
  text "'.date_Dossier'" at 191.5,-133.5 h1.4
  text "UNIT. :" at 142.5,-134.5 h1.05
  text "mm" at 154.5,-134.5 h1.4
  text "DOCUMENT REFERENCE" at 220.5,-138.5 h1.4
  text "ST MICROELECTRONICS" at 136.837,-140.021 h1.75
  text "PART NUMBER" at 213.5,-142.5 h1.4
  text "FORMAT" at 262.5,-142.5 h1.4
  text "SHEET" at 280.5,-142.5 h1.4
  text "SKY SOPHIA BATIMENT B" at 138.607,-143.101 h1.4
  text "776 RUE ALBERT CAQUOT" at 138.607,-146.101 h1.4
  text "3" at 266.5,-148.5 h2.1
  text "SOPHIA ANTIPOLIS" at 138.5,-149 h1.4
  text "06410 BIOT" at 138.727,-151.911 h1.4
  text ".Revision" at 281.6,-154.5 h1.5
  text "REV" at 286.5,-154.5 h1.4
  text "FRANCE" at 139,-155 h1.4
Cartouche Bottom:
  drawing of 437 lines, arcs and shapes, not listed
  text "DESIGNER" at -73.866,-108.5 h1.05
  text "EVOLUTION" at -37.866,-108.5 h1.05
  text "DATE" at -11.866,-108.5 h1.05
  text "REV" at -2.866,-108.5 h1.05
  text "DESIGNER" at 15.134,-108.5 h1.05
  text "EVOLUTION" at 50.134,-108.5 h1.05
  text "DATE" at 78.134,-108.5 h1.05
  text "REV" at -91.563,-108.701 h1.05
  text "TITLE :" at 76.497,-115.601 h2.1
  text ".Title" at 2.81,-116.216 h2.1
  text "GENERAL TOL." at -75.866,-116.5 h1.4
  text "+/- 0,2" at -77.866,-122.5 h1.75
  text "DOCUMENT :" at 76.497,-123.221 h2.1
  text "APPROVED" at -51.866,-128.5 h1.05
  text "CHECKED" at -23.866,-128.5 h1.05
  text "BE TECH" at 2.134,-129.5 h1.4
  text "DRAWN :" at 25.134,-129.5 h1.4
  text "SCALE :" at 52.134,-129.5 h1.05
  text "1/1" at 40.313,-130.216 h2.1
  text "'.date_Dossier'" at 2.134,-133.5 h1.4
  text "DATE :" at 24.134,-133.5 h1.4
  text "mm" at 39.134,-134.5 h1.4
  text "UNIT. :" at 51.134,-134.5 h1.05
  text "DOCUMENT REFERENCE" at -26.866,-138.5 h1.4
  text "ST MICROELECTRONICS" at 56.797,-140.021 h1.75
  text "SHEET" at -86.866,-142.5 h1.4
  text "FORMAT" at -68.866,-142.5 h1.4
  text "PART NUMBER" at -19.866,-142.5 h1.4
  text "SKY SOPHIA BATIMENT B" at 55.027,-143.101 h1.4
  text "776 RUE ALBERT CAQUOT" at 55.027,-146.101 h1.4
  text "3" at -72.866,-148.5 h2.1
  text "SOPHIA ANTIPOLIS" at 55.134,-149 h1.4
  text "06410 BIOT" at 54.907,-151.911 h1.4
  text ".Revision" at -88,-154.45 h1.5
  text "REV" at -92.866,-154.5 h1.4
  text "FRANCE" at 54.634,-155 h1.4
Board:
  drawing of 902 lines, arcs and shapes, not listed

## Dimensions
0,0 to 6.75,19.25 on Drill Drawing
0,0 to 6.75,19.25 on Drill Drawing
0,0 to 0,100 on Drill Drawing
0,0 to 84.5,0 on Drill Drawing
-0.5,-0.5 to -8.5,-8.5 on Drill Drawing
